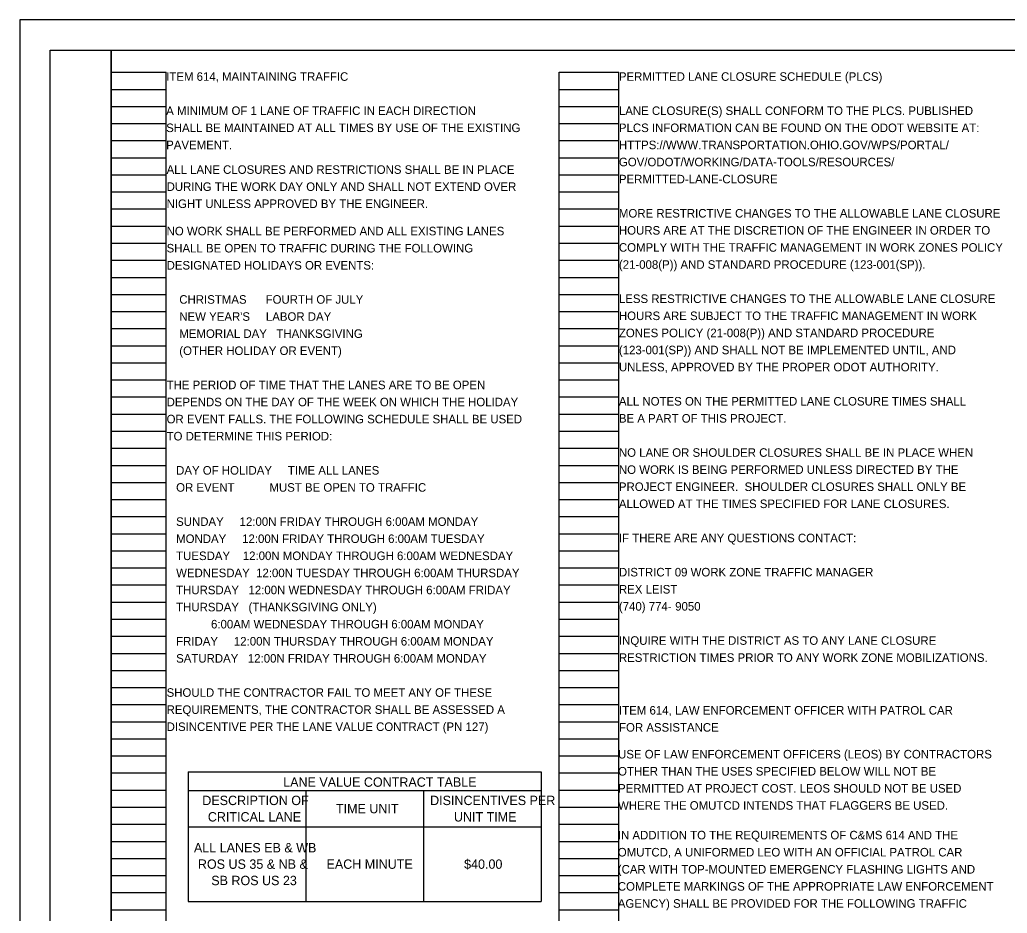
# Model space of a CAD drawing. Extents: x -32.5 to 8.4, y -16.3 to 12.1.
# Drawn here: x -25.61 to -9.43, y -2.5 to 12.14 of the extents above; entities that cross this region are included whole.
import ezdxf

# ---------------------------------------------------------------- set-up
doc = ezdxf.new("R2010")
doc.units = 0
for name, color, linetype in [('SH_Border', 7, 'Continuous'), ('SH_Cut_Line', 7, 'Continuous'), ('SH_Data', 7, 'Continuous'), ('SH_Text', 7, 'Continuous')]:
    doc.layers.add(name, color=color, linetype=linetype)

msp = doc.modelspace()

# ---------------------------------------------------------------- linework, layer by layer
at = {"layer": 'SH_Border'}
for points in [[(-25.111, 11.636), (-24.111, 11.636), (-24.111, -9.364), (-25.111, -9.364)], [(-24.111, 11.636), (7.889, 11.636), (7.889, -9.364), (-24.111, -9.364)]]:
    msp.add_lwpolyline(points, close=True, dxfattribs=at)
at = {"layer": 'SH_Cut_Line'}
msp.add_lwpolyline([(-25.611, -9.864), (8.389, -9.864), (8.389, 12.136), (-25.611, 12.136)], close=True, dxfattribs=at)
at = {"layer": 'SH_Data'}
for p, q in [((-24.111, -8.884), (-24.111, 11.276)), ((-24.111, 11.276), (-23.211, 11.276)), ((-23.211, -8.884), (-23.211, 11.276)), ((-16.771, -8.884), (-16.771, 11.276)), ((-16.771, 11.276), (-15.791, 11.276)), ((-15.791, -8.884), (-15.791, 11.276)), ((-24.111, 10.996), (-23.211, 10.996)), ((-16.771, 10.996), (-15.791, 10.996)), ((-24.111, 10.716), (-23.211, 10.716)), ((-16.771, 10.716), (-15.791, 10.716)), ((-24.111, 10.436), (-23.211, 10.436)), ((-16.771, 10.436), (-15.791, 10.436)), ((-24.111, 10.156), (-23.211, 10.156)), ((-16.771, 10.156), (-15.791, 10.156)), ((-24.111, 9.876), (-23.211, 9.876)), ((-16.771, 9.876), (-15.791, 9.876)), ((-24.111, 9.596), (-23.211, 9.596)), ((-16.771, 9.596), (-15.791, 9.596)), ((-24.111, 9.316), (-23.211, 9.316)), ((-16.771, 9.316), (-15.791, 9.316)), ((-24.111, 9.036), (-23.211, 9.036)), ((-16.771, 9.036), (-15.791, 9.036)), ((-24.111, 8.756), (-23.211, 8.756)), ((-16.771, 8.756), (-15.791, 8.756)), ((-24.111, 8.476), (-23.211, 8.476)), ((-16.771, 8.476), (-15.791, 8.476)), ((-24.111, 8.196), (-23.211, 8.196)), ((-16.771, 8.196), (-15.791, 8.196)), ((-24.111, 7.916), (-23.211, 7.916)), ((-16.771, 7.916), (-15.791, 7.916)), ((-24.111, 7.636), (-23.211, 7.636)), ((-16.771, 7.636), (-15.791, 7.636)), ((-24.111, 7.356), (-23.211, 7.356)), ((-16.771, 7.356), (-15.791, 7.356)), ((-24.111, 7.076), (-23.211, 7.076)), ((-16.771, 7.076), (-15.791, 7.076)), ((-24.111, 6.796), (-23.211, 6.796)), ((-16.771, 6.796), (-15.791, 6.796)), ((-24.111, 6.516), (-23.211, 6.516)), ((-16.771, 6.516), (-15.791, 6.516)), ((-24.111, 6.236), (-23.211, 6.236)), ((-16.771, 6.236), (-15.791, 6.236)), ((-24.111, 5.956), (-23.211, 5.956)), ((-16.771, 5.956), (-15.791, 5.956)), ((-24.111, 5.676), (-23.211, 5.676)), ((-16.771, 5.676), (-15.791, 5.676)), ((-24.111, 5.396), (-23.211, 5.396)), ((-16.771, 5.396), (-15.791, 5.396)), ((-24.111, 5.116), (-23.211, 5.116)), ((-16.771, 5.116), (-15.791, 5.116)), ((-24.111, 4.836), (-23.211, 4.836)), ((-16.771, 4.836), (-15.791, 4.836)), ((-24.111, 4.556), (-23.211, 4.556)), ((-16.771, 4.556), (-15.791, 4.556)), ((-24.111, 4.276), (-23.211, 4.276)), ((-16.771, 4.276), (-15.791, 4.276)), ((-24.111, 3.996), (-23.211, 3.996)), ((-16.771, 3.996), (-15.791, 3.996)), ((-24.111, 3.716), (-23.211, 3.716)), ((-16.771, 3.716), (-15.791, 3.716)), ((-24.111, 3.436), (-23.211, 3.436)), ((-16.771, 3.436), (-15.791, 3.436)), ((-24.111, 3.156), (-23.211, 3.156)), ((-16.771, 3.156), (-15.791, 3.156)), ((-24.111, 2.876), (-23.211, 2.876)), ((-16.771, 2.876), (-15.791, 2.876)), ((-24.111, 2.596), (-23.211, 2.596)), ((-16.771, 2.596), (-15.791, 2.596)), ((-24.111, 2.316), (-23.211, 2.316)), ((-16.771, 2.316), (-15.791, 2.316)), ((-24.111, 2.036), (-23.211, 2.036)), ((-16.771, 2.036), (-15.791, 2.036)), ((-24.111, 1.756), (-23.211, 1.756)), ((-16.771, 1.756), (-15.791, 1.756)), ((-24.111, 1.476), (-23.211, 1.476)), ((-16.771, 1.476), (-15.791, 1.476)), ((-24.111, 1.196), (-23.211, 1.196)), ((-16.771, 1.196), (-15.791, 1.196)), ((-24.111, 0.916), (-23.211, 0.916)), ((-16.771, 0.916), (-15.791, 0.916)), ((-24.111, 0.636), (-23.211, 0.636)), ((-16.771, 0.636), (-15.791, 0.636)), ((-24.111, 0.356), (-23.211, 0.356)), ((-16.771, 0.356), (-15.791, 0.356)), ((-24.111, 0.076), (-23.211, 0.076)), ((-16.771, 0.076), (-15.791, 0.076)), ((-24.111, -0.204), (-23.211, -0.204)), ((-16.771, -0.204), (-15.791, -0.204)), ((-24.111, -0.484), (-23.211, -0.484)), ((-16.771, -0.484), (-15.791, -0.484)), ((-24.111, -0.764), (-23.211, -0.764)), ((-16.771, -0.764), (-15.791, -0.764)), ((-24.111, -1.044), (-23.211, -1.044)), ((-16.771, -1.044), (-15.791, -1.044)), ((-24.111, -1.324), (-23.211, -1.324)), ((-16.771, -1.324), (-15.791, -1.324)), ((-24.111, -1.604), (-23.211, -1.604)), ((-16.771, -1.604), (-15.791, -1.604)), ((-24.111, -1.884), (-23.211, -1.884)), ((-16.771, -1.884), (-15.791, -1.884)), ((-24.111, -2.164), (-23.211, -2.164)), ((-16.771, -2.164), (-15.791, -2.164)), ((-24.111, -2.444), (-23.211, -2.444)), ((-16.771, -2.444), (-15.791, -2.444))]:
    msp.add_line(p, q, dxfattribs=at)
at = {"layer": 'SH_Text'}
for p, q in [((-22.849, -0.187), (-17.065, -0.187)), ((-22.849, -0.187), (-22.849, -2.31)), ((-17.065, -0.187), (-17.065, -2.31)), ((-22.849, -0.491), (-17.065, -0.491)), ((-20.921, -0.491), (-20.921, -2.31)), ((-18.993, -0.491), (-18.993, -2.31)), ((-22.849, -1.085), (-17.065, -1.085)), ((-22.849, -2.31), (-17.065, -2.31))]:
    msp.add_line(p, q, dxfattribs=at)

# ---------------------------------------------------------------- texts
for s, height, p in [('ITEM 614, MAINTAINING TRAFFIC ', 0.14, (-23.211, 11.136)), ('PERMITTED LANE CLOSURE SCHEDULE (PLCS)', 0.14, (-15.791, 11.136)), ('A MINIMUM OF 1 LANE OF TRAFFIC IN EACH DIRECTION', 0.14, (-23.211, 10.576)), ('LANE CLOSURE(S) SHALL CONFORM TO THE PLCS. PUBLISHED', 0.14, (-15.791, 10.576)), ('SHALL BE MAINTAINED AT ALL TIMES BY USE OF THE EXISTING', 0.14, (-23.211, 10.296)), ('PLCS INFORMATION CAN BE FOUND ON THE ODOT WEBSITE AT:', 0.14, (-15.791, 10.296)), ('PAVEMENT.', 0.14, (-23.211, 10.016)), ('HTTPS://WWW.TRANSPORTATION.OHIO.GOV/WPS/PORTAL/', 0.14, (-15.791, 10.016)), ('GOV/ODOT/WORKING/DATA-TOOLS/RESOURCES/', 0.14, (-15.791, 9.736)), ('ALL LANE CLOSURES AND RESTRICTIONS SHALL BE IN PLACE', 0.14, (-23.204, 9.612)), ('PERMITTED-LANE-CLOSURE', 0.14, (-15.791, 9.456)), ('DURING THE WORK DAY ONLY AND SHALL NOT EXTEND OVER', 0.14, (-23.204, 9.332)), ('NIGHT UNLESS APPROVED BY THE ENGINEER.', 0.14, (-23.204, 9.052)), ('MORE RESTRICTIVE CHANGES TO THE ALLOWABLE LANE CLOSURE', 0.14, (-15.791, 8.896)), ('NO WORK SHALL BE PERFORMED AND ALL EXISTING LANES', 0.14, (-23.204, 8.604)), ('HOURS ARE AT THE DISCRETION OF THE ENGINEER IN ORDER TO', 0.14, (-15.791, 8.616)), ('SHALL BE OPEN TO TRAFFIC DURING THE FOLLOWING', 0.14, (-23.204, 8.324)), ('COMPLY WITH THE TRAFFIC MANAGEMENT IN WORK ZONES POLICY', 0.14, (-15.791, 8.336)), ('DESIGNATED HOLIDAYS OR EVENTS:', 0.14, (-23.204, 8.044)), ('(21-008(P)) AND STANDARD PROCEDURE (123-001(SP)).', 0.14, (-15.791, 8.056)), ('    CHRISTMAS      FOURTH OF JULY', 0.14, (-23.204, 7.484)), ('LESS RESTRICTIVE CHANGES TO THE ALLOWABLE LANE CLOSURE', 0.14, (-15.791, 7.496)), ("    NEW YEAR'S     LABOR DAY", 0.14, (-23.204, 7.204)), ('HOURS ARE SUBJECT TO THE TRAFFIC MANAGEMENT IN WORK', 0.14, (-15.791, 7.216)), ('    MEMORIAL DAY   THANKSGIVING', 0.14, (-23.204, 6.924)), ('ZONES POLICY (21-008(P)) AND STANDARD PROCEDURE', 0.14, (-15.791, 6.936)), ('(123-001(SP)) AND SHALL NOT BE IMPLEMENTED UNTIL, AND', 0.14, (-15.791, 6.656)), ('    (OTHER HOLIDAY OR EVENT)', 0.14, (-23.204, 6.644)), ('UNLESS, APPROVED BY THE PROPER ODOT AUTHORITY.', 0.14, (-15.791, 6.376)), ('THE PERIOD OF TIME THAT THE LANES ARE TO BE OPEN', 0.14, (-23.204, 6.084)), ('DEPENDS ON THE DAY OF THE WEEK ON WHICH THE HOLIDAY', 0.14, (-23.204, 5.804)), ('ALL NOTES ON THE PERMITTED LANE CLOSURE TIMES SHALL ', 0.14, (-15.791, 5.816)), ('OR EVENT FALLS. THE FOLLOWING SCHEDULE SHALL BE USED', 0.14, (-23.204, 5.524)), ('BE A PART OF THIS PROJECT.', 0.14, (-15.791, 5.536)), ('TO DETERMINE THIS PERIOD:', 0.14, (-23.204, 5.244)), ('NO LANE OR SHOULDER CLOSURES SHALL BE IN PLACE WHEN ', 0.14, (-15.791, 4.976)), ('   DAY OF HOLIDAY     TIME ALL LANES', 0.14, (-23.204, 4.684)), ('NO WORK IS BEING PERFORMED UNLESS DIRECTED BY THE ', 0.14, (-15.791, 4.696)), ('   OR EVENT           MUST BE OPEN TO TRAFFIC', 0.14, (-23.204, 4.404)), ('PROJECT ENGINEER.  SHOULDER CLOSURES SHALL ONLY BE ', 0.14, (-15.791, 4.416)), ('ALLOWED AT THE TIMES SPECIFIED FOR LANE CLOSURES.', 0.14, (-15.791, 4.136)), ('   SUNDAY     12:00N FRIDAY THROUGH 6:00AM MONDAY', 0.14, (-23.204, 3.844)), ('   MONDAY     12:00N FRIDAY THROUGH 6:00AM TUESDAY', 0.14, (-23.204, 3.564)), ('IF THERE ARE ANY QUESTIONS CONTACT:', 0.14, (-15.791, 3.576)), ('   TUESDAY    12:00N MONDAY THROUGH 6:00AM WEDNESDAY', 0.14, (-23.204, 3.284)), ('   WEDNESDAY  12:00N TUESDAY THROUGH 6:00AM THURSDAY', 0.14, (-23.204, 3.004)), ('DISTRICT 09 WORK ZONE TRAFFIC MANAGER ', 0.14, (-15.791, 3.016)), ('   THURSDAY   12:00N WEDNESDAY THROUGH 6:00AM FRIDAY', 0.14, (-23.204, 2.724)), ('REX LEIST', 0.14, (-15.791, 2.736)), ('   THURSDAY   (THANKSGIVING ONLY)', 0.14, (-23.204, 2.444)), ('(740) 774-', 0.14, (-15.791, 2.456)), ('9050', 0.14, (-14.869, 2.456)), ('              6:00AM WEDNESDAY THROUGH 6:00AM MONDAY', 0.14, (-23.204, 2.164)), ('   FRIDAY     12:00N THURSDAY THROUGH 6:00AM MONDAY', 0.14, (-23.204, 1.884)), ('INQUIRE WITH THE DISTRICT AS TO ANY LANE CLOSURE ', 0.14, (-15.791, 1.896)), ('   SATURDAY   12:00N FRIDAY THROUGH 6:00AM MONDAY', 0.14, (-23.204, 1.604)), ('RESTRICTION TIMES PRIOR TO ANY WORK ZONE MOBILIZATIONS. ', 0.14, (-15.791, 1.616)), ('SHOULD THE CONTRACTOR FAIL TO MEET ANY OF THESE', 0.14, (-23.204, 1.044)), ('REQUIREMENTS, THE CONTRACTOR SHALL BE ASSESSED A', 0.14, (-23.204, 0.764)), ('ITEM 614, LAW ENFORCEMENT OFFICER WITH PATROL CAR', 0.14, (-15.789, 0.753)), ('DISINCENTIVE PER THE LANE VALUE CONTRACT (PN 127)', 0.14, (-23.204, 0.484)), ('FOR ASSISTANCE ', 0.14, (-15.789, 0.473)), ('USE OF LAW ENFORCEMENT OFFICERS (LEOS) BY CONTRACTORS', 0.14, (-15.805, 0.034)), ('OTHER THAN THE USES SPECIFIED BELOW WILL NOT BE', 0.14, (-15.805, -0.246)), ('LANE VALUE CONTRACT TABLE', 0.15339, (-21.293, -0.43)), ('PERMITTED AT PROJECT COST. LEOS SHOULD NOT BE USED', 0.14, (-15.805, -0.526)), ('DESCRIPTION OF ', 0.15339, (-22.619, -0.73)), ('DISINCENTIVES PER ', 0.15339, (-18.885, -0.73)), ('TIME UNIT', 0.1534, (-20.428, -0.864)), ('WHERE THE OMUTCD INTENDS THAT FLAGGERS BE USED.', 0.14, (-15.805, -0.806)), ('CRITICAL LANE', 0.15339, (-22.528, -0.999)), ('UNIT TIME', 0.1534, (-18.495, -0.999)), ('IN ADDITION TO THE REQUIREMENTS OF C&MS 614 AND THE', 0.14, (-15.809, -1.292)), ('ALL LANES EB & WB ', 0.15339, (-22.756, -1.505)), ('OMUTCD, A UNIFORMED LEO WITH AN OFFICIAL PATROL CAR', 0.14, (-15.809, -1.572)), ('ROS US 35 & NB & ', 0.15339, (-22.691, -1.774)), ('EACH MINUTE', 0.15339, (-20.583, -1.774)), ('$40.00', 0.1534, (-18.328, -1.774)), ('(CAR WITH TOP-MOUNTED EMERGENCY FLASHING LIGHTS AND', 0.14, (-15.809, -1.852)), ('SB ROS US 23', 0.15339, (-22.472, -2.042)), ('COMPLETE MARKINGS OF THE APPROPRIATE LAW ENFORCEMENT', 0.14, (-15.809, -2.132)), ('AGENCY) SHALL BE PROVIDED FOR THE FOLLOWING TRAFFIC', 0.14, (-15.809, -2.412))]:
    msp.add_text(s, height=height, dxfattribs=at).set_placement(p)

doc.saveas('drawing.dxf')
